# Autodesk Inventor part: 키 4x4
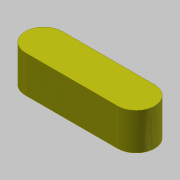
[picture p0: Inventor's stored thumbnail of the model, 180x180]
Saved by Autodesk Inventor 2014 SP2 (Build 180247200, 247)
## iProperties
Created: 2018-09
Part Number: 키 4x4
Document SubType Name: Modeling
Density: 7.86 g/cm^3
Material: 강철, 연강
Appearance: 노란색
Mass: 1.65269 g
Surface Area: 2.35398 cm^2
Volume: 0.210265 cm^3
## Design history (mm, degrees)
sketch "스케치1"
  geometry: L1 (-5, -2)-(5, -2); L2 (5, 2)-(-5, 2); A1 r 2 centre (5, 0) between (5, -2) and (5, 2); A2 r 2 centre (-5, 0) between (-5, 2) and (-5, -2); 2 further points
  constraints: 4 end point, 4 point on circle, 4 tangent, 2 centre point, 1 horizontal, 1 horizontal alignment, 1 midpoint, 1 parallel, 1 vertical alignment
  dimensions: "d0" = 4 distance between parallel lines of L1 L2; "d1" = 14 dimension on A1 A2
extrude "돌출1" new body sketch "스케치1" stored distance "d2" = 4; taper "d3" = 0 deg
node "솔리드1"
